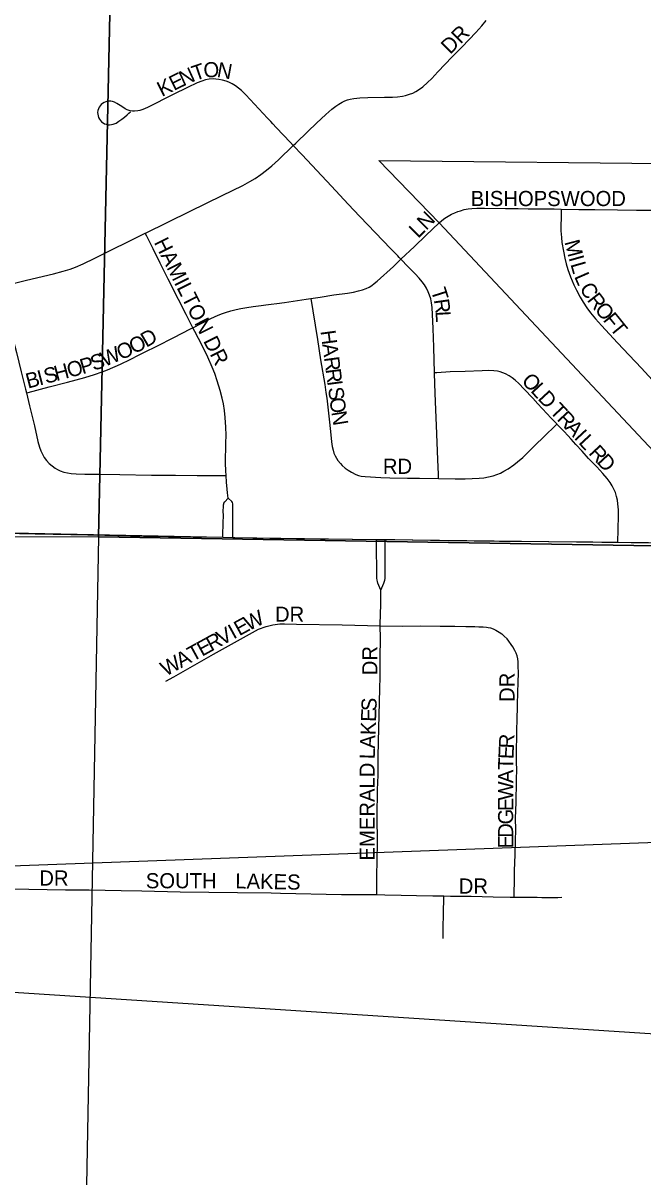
# Model space of a CAD drawing. Extents: x -5.6 to 34, y 0 to 22.
# Drawn here: x 7.358 to 8.177, y 18.084 to 19.608 of the extents above; entities that cross this region are included whole.
import ezdxf

# ---------------------------------------------------------------- set-up
doc = ezdxf.new("R2010")
doc.units = 0
for name, color, linetype in [('GM_X_City_Street', 7, 'Continuous'), ('GM_X_City_Street_Text', 7, 'Continuous'), ('GM_X_Corporation', 7, 'Continuous'), ('GM_X_Section', 7, 'Continuous'), ('GM_X_Township_Road', 7, 'Continuous'), ('GM_X_Township_Subdivision', 7, 'Continuous'), ('GM_X_Township_Subdivision_Text', 7, 'Continuous'), ('SH_Text', 7, 'Continuous')]:
    doc.layers.add(name, color=color, linetype=linetype)

msp = doc.modelspace()

# ---------------------------------------------------------------- linework, layer by layer
at = {"layer": 'GM_X_City_Street'}
for points in [[(7.7151, 19.4461), (7.7184, 19.4491), (7.7346, 19.4645), (7.746, 19.4754), (7.7584, 19.4871), (7.7662, 19.494), (7.7712, 19.498), (7.7754, 19.5009), (7.7798, 19.5035), (7.7832, 19.5051), (7.7867, 19.5064), (7.7904, 19.5074), (7.7954, 19.5083), (7.8031, 19.509), (7.8135, 19.5095), (7.8357, 19.5098), (7.8464, 19.51), (7.853, 19.5104), (7.8597, 19.5113), (7.8637, 19.5122), (7.8689, 19.5137), (7.873, 19.5151), (7.8773, 19.5175), (7.8832, 19.5214), (7.8864, 19.5238), (7.8924, 19.5292), (7.8981, 19.5348), (7.9064, 19.5432), (7.9253, 19.5633), (7.93, 19.5679), (7.9346, 19.5726), (7.9382, 19.5764), (7.9564, 19.5954), (7.9644, 19.6042), (7.9703, 19.6114)], [(7.7151, 19.4461), (7.7115, 19.4499), (7.6926, 19.47), (7.6881, 19.4747), (7.6854, 19.4777), (7.6809, 19.4824), (7.6523, 19.5131), (7.6467, 19.5186), (7.6429, 19.522), (7.6389, 19.5251), (7.6346, 19.5277), (7.6301, 19.5299), (7.6265, 19.5312), (7.6216, 19.5325), (7.6166, 19.5335), (7.6126, 19.5339), (7.6091, 19.5341), (7.6041, 19.5337), (7.5992, 19.5327), (7.5943, 19.5312), (7.5883, 19.5289), (7.5754, 19.5227), (7.5565, 19.5136), (7.5224, 19.4965), (7.5162, 19.4938), (7.5123, 19.4925), (7.5096, 19.4918), (7.5054, 19.4914), (7.5025, 19.4916), (7.4997, 19.492), (7.4957, 19.4934), (7.4932, 19.4947), (7.4885, 19.4975), (7.482, 19.5017), (7.4787, 19.5034), (7.4764, 19.5041), (7.4741, 19.5046), (7.4718, 19.5048), (7.4695, 19.5045), (7.4673, 19.5039), (7.4651, 19.503), (7.4632, 19.5018), (7.4614, 19.5003), (7.4598, 19.4985), (7.4585, 19.4966), (7.4576, 19.4945), (7.4569, 19.4923), (7.4566, 19.4899), (7.4567, 19.4876), (7.4571, 19.4853), (7.4579, 19.4831), (7.4589, 19.481), (7.4603, 19.4791), (7.4619, 19.4774), (7.4637, 19.476), (7.4657, 19.4749), (7.4679, 19.4741), (7.4702, 19.4736), (7.4725, 19.4735), (7.4749, 19.4737), (7.4772, 19.4743), (7.4809, 19.4758), (7.4848, 19.4781), (7.4888, 19.4809), (7.4923, 19.4835), (7.4955, 19.4866), (7.4978, 19.4886), (7.5, 19.4906)], [(7.5196, 19.3304), (7.5198, 19.3304), (7.5788, 19.3592), (7.6213, 19.38), (7.6484, 19.3934), (7.6577, 19.3984), (7.6646, 19.4025), (7.6722, 19.4078), (7.6796, 19.4134), (7.6867, 19.4194), (7.6955, 19.4274), (7.7151, 19.4461)], [(7.8574, 19.2958), (7.855, 19.2982), (7.8533, 19.3002), (7.8514, 19.3021), (7.8506, 19.3031), (7.8442, 19.3097), (7.8033, 19.3524), (7.7879, 19.3686), (7.7656, 19.3926), (7.7269, 19.4337), (7.7151, 19.4461)], [(7.8574, 19.2958), (7.8752, 19.3129), (7.8905, 19.3273), (7.908, 19.3439)], [(7.3277, 19.2594), (7.3626, 19.2681), (7.3984, 19.2768), (7.4112, 19.2801), (7.4201, 19.2829), (7.4275, 19.2856), (7.4373, 19.2897), (7.4528, 19.2971), (7.5196, 19.3304)], [(7.5826, 19.2053), (7.5738, 19.2227), (7.5635, 19.2426), (7.55, 19.2696), (7.5393, 19.2907), (7.5302, 19.3096), (7.5217, 19.3262), (7.5196, 19.3304)], [(7.7382, 19.2441), (7.7507, 19.246), (7.7687, 19.249), (7.7869, 19.2512), (7.7948, 19.2525), (7.8013, 19.254), (7.8065, 19.2554), (7.8116, 19.2573), (7.8153, 19.2591), (7.8188, 19.2613), (7.8221, 19.2637), (7.8262, 19.2671), (7.8477, 19.2865), (7.8574, 19.2958)], [(7.9017, 19.1458), (7.9009, 19.1798), (7.9, 19.2046), (7.8987, 19.2321), (7.898, 19.2385), (7.8969, 19.2435), (7.8954, 19.2483), (7.8935, 19.253), (7.8912, 19.2575), (7.8885, 19.2619), (7.8855, 19.266), (7.8814, 19.2709), (7.8761, 19.2766), (7.8668, 19.2858), (7.8574, 19.2958)], [(7.3277, 19.2594), (7.3345, 19.2312), (7.3397, 19.2095), (7.3492, 19.1726), (7.3556, 19.1471), (7.3613, 19.1242), (7.3624, 19.1193)], [(7.5826, 19.2053), (7.6064, 19.2174), (7.6158, 19.2219), (7.6217, 19.2244), (7.6254, 19.2256), (7.6328, 19.2278), (7.6399, 19.2295), (7.6458, 19.2307), (7.654, 19.2322), (7.6621, 19.2335), (7.6728, 19.235), (7.6791, 19.2358), (7.686, 19.2365), (7.6935, 19.2373), (7.7035, 19.2389), (7.7324, 19.2432), (7.7382, 19.2441)], [(7.7382, 19.2441), (7.7409, 19.2276), (7.7471, 19.19), (7.7512, 19.1628), (7.7567, 19.1304), (7.7583, 19.12), (7.7595, 19.1126), (7.7614, 19.0965), (7.7632, 19.0809), (7.7649, 19.0639), (7.7657, 19.0548), (7.7667, 19.0484), (7.7678, 19.0435), (7.7689, 19.0399), (7.7704, 19.0364), (7.7721, 19.0331), (7.7742, 19.03), (7.7774, 19.0261), (7.78, 19.0233), (7.7838, 19.02), (7.7879, 19.0171), (7.7923, 19.0145), (7.798, 19.0116), (7.8015, 19.0103), (7.8051, 19.0095), (7.8101, 19.009), (7.831, 19.0074), (7.8427, 19.0071), (7.8663, 19.0068), (7.8795, 19.0067), (7.8821, 19.0066), (7.907, 19.0064), (7.9073, 19.0064)], [(7.3624, 19.1193), (7.3646, 19.1199), (7.3924, 19.1273), (7.4169, 19.1337), (7.4398, 19.1399), (7.4524, 19.1437), (7.4624, 19.1471), (7.4698, 19.15), (7.4867, 19.1575), (7.4998, 19.1636), (7.5116, 19.1695), (7.5421, 19.1847), (7.5502, 19.189), (7.5572, 19.1927), (7.5795, 19.2038), (7.5826, 19.2053)], [(7.6263, 19.0103), (7.626, 19.0162), (7.6257, 19.0267), (7.6261, 19.053), (7.6263, 19.0635), (7.626, 19.0739), (7.6251, 19.0869), (7.6242, 19.096), (7.6228, 19.1049), (7.6212, 19.1126), (7.6186, 19.1226), (7.6148, 19.1351), (7.6114, 19.145), (7.608, 19.1534), (7.6021, 19.1665), (7.5947, 19.1818), (7.585, 19.2005), (7.5826, 19.2053)], [(8.0636, 19.0781), (8.0634, 19.0783), (8.0607, 19.0812), (8.0557, 19.0866), (8.0509, 19.0917), (8.0443, 19.0988), (8.0383, 19.1051), (8.0316, 19.1123), (8.0203, 19.1242), (8.0132, 19.1318), (8.0085, 19.1361), (8.0045, 19.1393), (8.0003, 19.1421), (7.9958, 19.1445), (7.9923, 19.146), (7.9888, 19.1472), (7.9851, 19.148), (7.9801, 19.1487), (7.9738, 19.149), (7.9647, 19.1487), (7.9424, 19.1476), (7.9227, 19.1471), (7.905, 19.146), (7.9017, 19.1458)], [(7.9073, 19.0064), (7.907, 19.0114), (7.9061, 19.0314), (7.9043, 19.0761), (7.903, 19.1075), (7.9021, 19.1312), (7.9017, 19.1458)], [(7.3624, 19.1193), (7.3664, 19.1024), (7.373, 19.0757), (7.3777, 19.0552), (7.3798, 19.0477), (7.3815, 19.0429), (7.3836, 19.0383), (7.3861, 19.034), (7.3891, 19.0299), (7.3925, 19.0263), (7.3964, 19.023), (7.4005, 19.02), (7.4037, 19.0181), (7.4071, 19.0165), (7.4119, 19.0148), (7.4168, 19.0136), (7.4218, 19.0128), (7.4282, 19.0123), (7.4399, 19.0121), (7.4597, 19.0119), (7.4859, 19.0114), (7.5279, 19.0108), (7.5594, 19.0106), (7.5883, 19.0104), (7.608, 19.0102), (7.622, 19.0103), (7.6263, 19.0103)], [(7.9073, 19.0064), (7.9293, 19.0059), (7.9424, 19.006), (7.9607, 19.0066), (7.967, 19.0072), (7.9733, 19.0083), (7.9795, 19.0099), (7.9844, 19.0116), (7.9891, 19.0135), (7.9936, 19.0159), (7.9991, 19.0192), (8.0066, 19.0243), (8.0117, 19.0282), (8.0185, 19.0342), (8.0336, 19.0488), (8.0477, 19.0625), (8.0613, 19.0758), (8.0636, 19.0781)], [(8.1441, 18.9221), (8.1445, 18.939), (8.1451, 18.9573), (8.1449, 18.965), (8.1443, 18.9727), (8.1436, 18.9778), (8.1425, 18.9827), (8.1409, 18.9876), (8.139, 18.9922), (8.1366, 18.9967), (8.1339, 19.0011), (8.1301, 19.0062), (8.1242, 19.013), (8.1162, 19.0216), (8.1055, 19.0326), (8.0969, 19.0422), (8.0888, 19.0512), (8.0824, 19.0583), (8.0781, 19.0629), (8.0731, 19.0682), (8.068, 19.0736), (8.0662, 19.0755), (8.0636, 19.0781)], [(7.6292, 18.9804), (7.6283, 18.9872), (7.6278, 18.9924), (7.6268, 19.0016), (7.6263, 19.0103)], [(7.6222, 18.9287), (7.6222, 18.9314), (7.6226, 18.9474), (7.6228, 18.958), (7.6227, 18.9625), (7.6228, 18.9696), (7.6229, 18.9714), (7.6232, 18.9727), (7.6236, 18.9735), (7.6249, 18.9753), (7.6292, 18.9804)], [(7.6355, 18.9285), (7.6355, 18.9306), (7.6355, 18.9612), (7.6354, 18.9651), (7.6355, 18.9702), (7.6355, 18.9716), (7.6353, 18.973), (7.6348, 18.9746), (7.6338, 18.9758), (7.6292, 18.9804)]]:
    msp.add_lwpolyline(points, dxfattribs=at)
at = {"layer": 'GM_X_Corporation'}
msp.add_lwpolyline([(6.4578, 18.9257), (6.4691, 18.9327), (6.4761, 18.9365), (6.4841, 18.94), (6.4957, 18.9442), (6.5125, 18.9483), (6.5212, 18.9494), (6.5298, 18.9502), (6.545, 18.9507), (6.5992, 18.9496), (6.6256, 18.9497), (6.9854, 18.9417), (7.0015, 18.9415), (7.6222, 18.9287), (7.6355, 18.9285), (7.8251, 18.9258), (7.8363, 18.9257), (8.3062, 18.9202), (7.908, 19.3439), (7.8283, 19.4265), (8.2463, 19.4221), (8.5459, 19.9586)], dxfattribs=at)
at = {"layer": 'GM_X_Section'}
for points in [[(7.5006, 20.9), (7.2498, 20.9), (7.2609, 20.8761), (5.343, 19.9706), (5.3166, 18.9352), (7.4578, 18.9294)], [(8.9, 18.906), (8.9, 20.9), (7.5006, 20.9), (7.4578, 18.9294)], [(5.3166, 18.9352), (7.4578, 18.9294), (7.4183, 16.7871), (5.2895, 16.8144)], [(8.9, 16.7658), (8.9, 18.906), (7.4578, 18.9294), (7.4183, 16.7871)]]:
    msp.add_lwpolyline(points, close=True, dxfattribs=at)
at = {"layer": 'GM_X_Township_Road'}
for points in [[(7.0016, 18.9415), (7.0025, 18.9415), (7.0223, 18.9415), (7.0813, 18.9404), (7.1115, 18.9396), (7.1456, 18.9385), (7.1693, 18.9381), (7.2533, 18.9361), (7.2875, 18.9352), (7.3151, 18.9346), (7.3321, 18.9342), (7.3741, 18.9333), (7.4214, 18.9322), (7.4661, 18.9315), (7.5173, 18.9302), (7.583, 18.9291), (7.6222, 18.9287)], [(7.6222, 18.9287), (7.6355, 18.9285)], [(7.6355, 18.9285), (7.6381, 18.9285), (7.6618, 18.928), (7.6841, 18.9276), (7.7196, 18.927), (7.7511, 18.9267), (7.7931, 18.9261), (7.8251, 18.9258)], [(7.8251, 18.9258), (7.8363, 18.9257)], [(7.8363, 18.9257), (7.8496, 18.9256), (7.9205, 18.9244), (7.9875, 18.9234), (8.0072, 18.9233), (8.0978, 18.9228), (8.111, 18.9225), (8.1228, 18.9224), (8.1441, 18.9221)], [(8.1441, 18.9221), (8.1688, 18.9218), (8.1845, 18.9216), (8.2463, 18.9212), (8.3062, 18.9202)]]:
    msp.add_lwpolyline(points, dxfattribs=at)
at = {"layer": 'GM_X_Township_Subdivision'}
for points in [[(7.908, 19.3439), (7.9114, 19.3471), (7.9155, 19.3501), (7.9198, 19.3529), (7.9243, 19.3553), (7.9285, 19.3573), (7.9325, 19.3589), (7.9362, 19.36), (7.9411, 19.3614), (7.9461, 19.3624), (7.9512, 19.363), (7.9576, 19.3633), (7.968, 19.3634), (7.9955, 19.363), (8.006, 19.363), (8.0126, 19.3629), (8.0257, 19.3626), (8.0376, 19.3626), (8.0599, 19.3624), (8.0691, 19.3622)], [(8.0691, 19.3622), (8.0691, 19.3576), (8.0689, 19.3334), (8.0695, 19.3244), (8.0702, 19.3179), (8.0721, 19.3064), (8.074, 19.2975), (8.0758, 19.2899), (8.078, 19.2824), (8.0815, 19.2727), (8.0859, 19.2619), (8.0893, 19.2549), (8.0943, 19.2457), (8.0982, 19.239), (8.1033, 19.2315), (8.1079, 19.2253), (8.1145, 19.2172), (8.1223, 19.2085), (8.1437, 19.1854), (8.1592, 19.1693), (8.1753, 19.1521), (8.1895, 19.1366)], [(8.0691, 19.3622), (8.0927, 19.3617), (8.1137, 19.3617), (8.1438, 19.3613), (8.1687, 19.3608), (8.1897, 19.3605), (8.1975, 19.3603)], [(7.8309, 18.8589), (7.827, 18.8681), (7.8263, 18.8704), (7.8259, 18.8722), (7.8258, 18.8746), (7.8252, 18.9239), (7.8251, 18.9258)], [(7.8309, 18.8589), (7.835, 18.8679), (7.8359, 18.8705), (7.8363, 18.8722), (7.8365, 18.874), (7.8364, 18.8777), (7.8366, 18.8855), (7.8366, 18.9088), (7.8364, 18.9235), (7.8363, 18.9257)], [(7.8302, 18.8118), (7.8302, 18.8138), (7.831, 18.84), (7.8309, 18.8589)], [(7.5469, 18.7385), (7.5572, 18.7442), (7.6096, 18.7743), (7.6452, 18.7939), (7.6694, 18.8072), (7.6792, 18.811), (7.6881, 18.8132), (7.6972, 18.8141), (7.7037, 18.8141)], [(7.7037, 18.8141), (7.7195, 18.814), (7.7799, 18.813), (7.8302, 18.8118)], [(7.8254, 18.4567), (7.8254, 18.4603), (7.8257, 18.4818), (7.8261, 18.5011), (7.8264, 18.526), (7.826, 18.5598), (7.8266, 18.5949), (7.8272, 18.6144), (7.8273, 18.6279), (7.8273, 18.638), (7.8277, 18.6591), (7.8295, 18.7286), (7.8299, 18.7443), (7.8299, 18.7692), (7.8303, 18.7954), (7.8302, 18.8118)], [(7.8302, 18.8118), (7.8596, 18.8113), (7.8831, 18.8115), (7.9093, 18.8113), (7.9289, 18.8112), (7.9433, 18.8108), (7.9473, 18.8106), (7.9552, 18.8108), (7.9604, 18.8105), (7.9641, 18.8103), (7.9662, 18.8103), (7.9706, 18.81), (7.9728, 18.8096), (7.9757, 18.809), (7.9794, 18.8077), (7.983, 18.8059), (7.9874, 18.8032), (7.9906, 18.801), (7.994, 18.7982), (7.998, 18.7944)], [(8.0072, 18.4533), (8.0073, 18.4575), (8.0074, 18.4758), (8.0075, 18.4881), (8.0082, 18.5095), (8.0088, 18.5277), (8.0093, 18.5427), (8.009, 18.5571), (8.0096, 18.5789), (8.0098, 18.5876), (8.01, 18.5972), (8.0103, 18.6104), (8.0106, 18.62), (8.0104, 18.6331), (8.0103, 18.6475), (8.0107, 18.6659), (8.0108, 18.6764), (8.011, 18.6855), (8.0115, 18.7079), (8.0121, 18.7236), (8.0122, 18.7367), (8.0127, 18.7498), (8.0123, 18.7586), (8.0123, 18.7643), (8.0119, 18.7681), (8.011, 18.772), (8.0096, 18.7756), (8.008, 18.7792), (8.0053, 18.7838), (7.998, 18.7944)], [(7.2205, 18.4652), (7.2211, 18.4652), (7.292, 18.4646), (7.3354, 18.4642), (7.3656, 18.4637), (7.4141, 18.463), (7.4453, 18.463), (7.4876, 18.4622), (7.5151, 18.4617)], [(7.5151, 18.4617), (7.5655, 18.4605), (7.6415, 18.4593), (7.6861, 18.459), (7.6983, 18.4587)], [(7.6983, 18.4587), (7.7791, 18.4569), (7.8254, 18.4567)], [(7.8254, 18.4567), (7.8361, 18.4563), (7.8576, 18.4559), (7.878, 18.4555), (7.8994, 18.4551), (7.9143, 18.4549)], [(7.9133, 18.3989), (7.9133, 18.4102), (7.9138, 18.4338), (7.9142, 18.451), (7.9143, 18.4549)], [(7.9143, 18.4549), (7.9229, 18.4547), (7.9504, 18.4546), (7.9793, 18.4539), (8.0016, 18.4535), (8.0072, 18.4533)], [(8.0072, 18.4533), (8.0252, 18.4532), (8.0373, 18.4531), (8.0438, 18.453), (8.0528, 18.453), (8.0594, 18.4529), (8.0648, 18.453), (8.0701, 18.4532)]]:
    msp.add_lwpolyline(points, dxfattribs=at)
at = {"layer": 'SH_Text'}
msp.add_lwpolyline([(10.6219, 18.1148), (5.6964, 18.4344), (10.6219, 18.6148)], close=True, dxfattribs=at)

# ---------------------------------------------------------------- texts
at = {"layer": 'GM_X_City_Street_Text'}
for s, rotation, p in [('DR', 45, (7.9224, 19.5657)), ('T', 19.0915, (7.5853, 19.5312)), ('O', 4.3099, (7.5972, 19.5355)), ('N', 349.6502, (7.6134, 19.5369)), ('E', 26.4429, (7.5573, 19.5179)), ('N', 24.3752, (7.5697, 19.5241)), ('K', 26.4575, (7.5415, 19.5101)), ('LN', 45, (7.8802, 19.3228)), ('HAMILTON DR', 296.567, (7.5307, 19.3183)), ('T', 287.4502, (7.8968, 19.2549)), ('R', 278.2125, (7.9009, 19.2423)), ('L', 273.3617, (7.9031, 19.227)), ('O', 27.8752, (7.5046, 19.1701)), ('D', 30.389, (7.521, 19.1788)), ('H', 277.6077, (7.7511, 19.201)), ('W', 22.9321, (7.4657, 19.1534)), ('O', 23.3475, (7.4869, 19.1624)), ('A', 277.6077, (7.7534, 19.1836)), ('H', 14.7202, (7.4019, 19.1348)), ('O', 14.7388, (7.4189, 19.1392)), ('P', 16.4934, (7.4366, 19.1439)), ('S', 19.3867, (7.4512, 19.1482)), ('R', 277.5979, (7.7557, 19.1661)), ('B', 14.7312, (7.3645, 19.1249)), ('I', 14.7427, (7.3798, 19.1289)), ('S', 14.7519, (7.3883, 19.1312)), ('R', 277.6282, (7.7578, 19.1504)), ('O', 312.9132, (8.0158, 19.1344)), ('I', 277.6293, (7.7599, 19.1347)), ('L', 312.9308, (8.0278, 19.1216)), ('S', 277.5892, (7.7611, 19.126)), ('O', 277.61, (7.7629, 19.112)), ('D', 312.9451, (8.0374, 19.1112)), ('T', 312.9132, (8.053, 19.0945)), ('R', 312.9221, (8.0626, 19.0842)), ('N', 279.2352, (7.7654, 19.094)), ('A', 312.9292, (8.0734, 19.0726)), ('I', 312.9423, (8.0853, 19.0597)), ('L', 312.9132, (8.0913, 19.0532)), ('R', 312.9221, (8.1045, 19.0391)), ('D', 312.9292, (8.1153, 19.0275)), ('RD', 0, (7.8336, 19.0124))]:
    msp.add_text(s, height=0.02, rotation=rotation, dxfattribs=at).set_placement(p)
at = {"layer": 'GM_X_Township_Subdivision_Text'}
for s, rotation, p in [('BISHOPSWOOD', 0, (7.9497, 19.3661)), ('M', 284.7121, (8.0734, 19.3188)), ('I', 285.9619, (8.0789, 19.2979)), ('L', 285.9116, (8.0813, 19.2895)), ('L', 293.4973, (8.0861, 19.2732)), ('C', 300.5543, (8.0929, 19.2579)), ('R', 307.942, (8.1026, 19.2419)), ('O', 309.0565, (8.1126, 19.2291)), ('F', 309.0395, (8.1237, 19.2154)), ('T', 309.045, (8.1325, 19.2045)), ('DR', 0, (7.691, 18.817)), ('E', 28.8102, (7.6438, 18.7978)), ('W', 25.7229, (7.6559, 18.8045)), ('V', 28.8136, (7.6207, 18.7851)), ('I', 28.7744, (7.6361, 18.7936)), ('E', 28.8132, (7.5945, 18.7707)), ('R', 28.781, (7.6068, 18.7775)), ('A', 28.7744, (7.5667, 18.7554)), ('T', 28.8102, (7.5821, 18.7639)), ('DR', 90, (7.8263, 18.7464)), ('W', 28.8064, (7.5466, 18.7444)), ('DR', 90, (8.0076, 18.7112)), ('S', 87.8961, (7.825, 18.6986)), ('E', 87.9193, (7.8245, 18.6846)), ('K', 87.9234, (7.8239, 18.667)), ('A', 87.9452, (7.8232, 18.6494)), ('R', 87.2309, (8.0067, 18.6493)), ('L', 88.1691, (7.8228, 18.6353)), ('E', 87.4309, (8.0061, 18.6353)), ('EMERALD', 90, (7.8228, 18.5017)), ('T', 89.153, (8.0058, 18.6214)), ('A', 89.9781, (8.0058, 18.6038)), ('W', 89.9832, (8.0058, 18.581)), ('E', 89.9956, (8.0058, 18.5669)), ('G', 89.9781, (8.0058, 18.5493)), ('D', 89.9928, (8.0058, 18.5317)), ('E', 89.9727, (8.0058, 18.5176)), ('DR', 0, (7.3795, 18.4686)), ('SOUTH', 0, (7.5203, 18.465)), ('LAKES', 358.7234, (7.6384, 18.465)), ('DR', 0, (7.9339, 18.458))]:
    msp.add_text(s, height=0.02, rotation=rotation, dxfattribs=at).set_placement(p)

doc.saveas('drawing.dxf')
